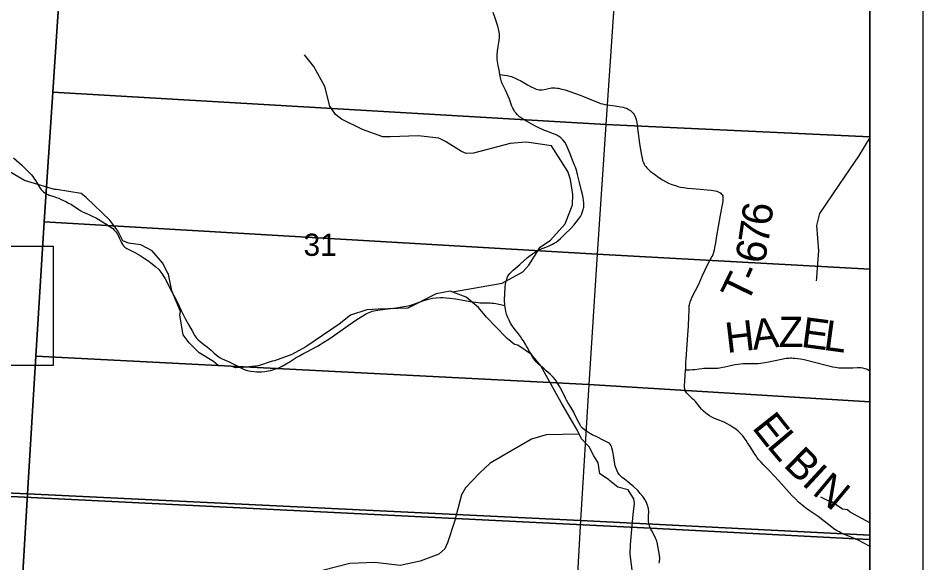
# Model space of a CAD drawing. Extents: x 0 to 34, y 0 to 22.
# Drawn here: x 7.297 to 9, y 19.136 to 20.161 of the extents above; entities that cross this region are included whole.
import ezdxf

# ---------------------------------------------------------------- set-up
doc = ezdxf.new("R2010")
doc.units = 0
for name, color, linetype in [('Default', 7, 'Continuous'), ('GM_X_County_Road', 7, 'Continuous'), ('GM_X_Minor_River', 7, 'Continuous'), ('GM_X_Section', 7, 'Continuous'), ('GM_X_Section_Text', 7, 'Continuous'), ('GM_X_Township_Road', 7, 'Continuous'), ('GM_X_Township_Road_Text', 7, 'Continuous'), ('SH_Cut_Line', 7, 'Continuous'), ('SH_Data', 7, 'Continuous'), ('TX_P_1', 7, 'Continuous')]:
    doc.layers.add(name, color=color, linetype=linetype)

msp = doc.modelspace()

# ---------------------------------------------------------------- linework, layer by layer
at = {"layer": 'Default'}
for points in [[(7.1944, 19.2649), (8.4872, 19.2008), (8.8731, 19.181), (8.9, 19.1797), (8.9, 20.9), (6.3694, 20.9)], [(8.9, 14.1), (8.9, 19.1797), (8.8731, 19.181), (8.4872, 19.2008), (7.1944, 19.2649), (6.2536, 19.3066), (6.2282, 18.9116), (6.1917, 18.3385), (6.1723, 18.0255), (6.1151, 17.0743), (6.0901, 16.6706), (6.0633, 16.2368)]]:
    msp.add_lwpolyline(points, dxfattribs=at)
for points in [[(8.9, 19.9376), (8.9, 20.1978), (8.4216, 20.2279), (8.4033, 19.9608)], [(8.9, 19.6886), (8.9, 19.9376), (8.4033, 19.9608), (8.3873, 19.7165)], [(8.9, 19.4386), (8.9, 19.6886), (8.3873, 19.7165), (8.3712, 19.4714)], [(8.9, 19.1878), (8.9, 19.4386), (8.3712, 19.4714), (8.3558, 19.2156)], [(8.9, 18.1799), (8.9, 19.1878), (8.3558, 19.2156), (8.299, 18.2095)]]:
    msp.add_lwpolyline(points, close=True, dxfattribs=at)
at = {"layer": 'GM_X_County_Road'}
for points in [[(8.2041, 20.0548), (8.2025, 20.0637), (8.2006, 20.0718), (8.1993, 20.0795), (8.1988, 20.0832), (8.1987, 20.0869), (8.1988, 20.091), (8.1996, 20.0992), (8.2009, 20.1078), (8.2021, 20.1151), (8.2027, 20.1197), (8.2029, 20.1237), (8.203, 20.1276), (8.2029, 20.1311), (8.2026, 20.1345), (8.2021, 20.1375), (8.2015, 20.1409), (8.2002, 20.1456), (8.1948, 20.1609), (8.1913, 20.1715)], [(8.2771, 19.5092), (8.2745, 19.5116), (8.2723, 19.5138), (8.2702, 19.5164), (8.2675, 19.52), (8.2645, 19.5249), (8.2616, 19.5302), (8.2598, 19.5335), (8.256, 19.5405), (8.2541, 19.5436), (8.2525, 19.5461), (8.2481, 19.5535), (8.2453, 19.5576), (8.2425, 19.5617), (8.2387, 19.5666), (8.2308, 19.5767), (8.2263, 19.583), (8.224, 19.5867), (8.2211, 19.5922), (8.2189, 19.5974), (8.2166, 19.6039), (8.2153, 19.6088), (8.2142, 19.6136), (8.2136, 19.617), (8.2132, 19.6201), (8.213, 19.6231), (8.2127, 19.6267), (8.2127, 19.6309), (8.2132, 19.6425), (8.2139, 19.6544), (8.2147, 19.6606), (8.2157, 19.666), (8.2167, 19.6693), (8.2177, 19.6722), (8.2191, 19.675), (8.2208, 19.6778), (8.2227, 19.6803), (8.225, 19.683), (8.2287, 19.6864), (8.2413, 19.6975), (8.2561, 19.7105), (8.261, 19.7144), (8.265, 19.7173), (8.2689, 19.7197), (8.273, 19.7221), (8.2773, 19.7243), (8.2838, 19.7272), (8.292, 19.7304), (8.2989, 19.7334), (8.3029, 19.7353), (8.3063, 19.7372), (8.3097, 19.7396), (8.3132, 19.7421), (8.3183, 19.7465), (8.3268, 19.7547), (8.3365, 19.7643), (8.3428, 19.7711), (8.3476, 19.7768), (8.352, 19.7827), (8.3554, 19.7879), (8.3579, 19.7928), (8.3596, 19.7968), (8.3609, 19.8008), (8.3614, 19.803), (8.3617, 19.805), (8.3621, 19.8092), (8.362, 19.8135), (8.3614, 19.8183), (8.3608, 19.8224), (8.3599, 19.8266), (8.3576, 19.8361), (8.3538, 19.8519), (8.3503, 19.8667), (8.3487, 19.872), (8.3473, 19.8766), (8.346, 19.8802), (8.3444, 19.8841), (8.3406, 19.8935), (8.3359, 19.9053), (8.3305, 19.9188), (8.3284, 19.9232), (8.326, 19.9275), (8.3226, 19.9318), (8.3208, 19.9337), (8.3188, 19.9355), (8.3157, 19.9379), (8.3131, 19.9395), (8.3111, 19.9407), (8.3088, 19.9417), (8.3059, 19.9428), (8.2952, 19.9467), (8.2916, 19.9481), (8.2879, 19.9496), (8.2841, 19.9513), (8.28, 19.9533), (8.2712, 19.9579), (8.2631, 19.9622), (8.2497, 19.9694), (8.2444, 19.9726), (8.2409, 19.9753), (8.2372, 19.9787), (8.2343, 19.9819), (8.2317, 19.9855), (8.2301, 19.9881), (8.2285, 19.9912), (8.2266, 19.9954), (8.2245, 20.0009), (8.2218, 20.0082), (8.2195, 20.0138), (8.217, 20.0198), (8.2144, 20.0252), (8.2117, 20.0304), (8.2093, 20.0354), (8.2076, 20.0389), (8.2068, 20.041), (8.2062, 20.0434), (8.2056, 20.0459), (8.2041, 20.0548)], [(8.4879, 19.1994), (8.4874, 19.2003), (8.4869, 19.2014), (8.4854, 19.2055), (8.4846, 19.2079), (8.4841, 19.2104), (8.4837, 19.2128), (8.4835, 19.2154), (8.4835, 19.2182), (8.4836, 19.2216), (8.4839, 19.226), (8.4841, 19.2303), (8.4841, 19.2339), (8.4839, 19.236), (8.4836, 19.238), (8.4831, 19.2402), (8.4825, 19.2422), (8.4812, 19.2457), (8.4796, 19.2493), (8.4766, 19.2552), (8.4729, 19.2609), (8.4682, 19.2665), (8.4633, 19.2719), (8.4552, 19.2797), (8.4499, 19.2841), (8.4447, 19.2882), (8.4383, 19.2931), (8.4339, 19.2967), (8.4303, 19.3002), (8.4286, 19.3021), (8.4271, 19.304), (8.4259, 19.3055), (8.425, 19.3072), (8.4237, 19.3099), (8.4225, 19.3133), (8.4211, 19.3186), (8.4197, 19.3253), (8.4176, 19.3382), (8.4169, 19.3425), (8.4158, 19.3479), (8.4147, 19.3521), (8.4137, 19.3549), (8.4127, 19.357), (8.4114, 19.3589), (8.41, 19.3605), (8.4082, 19.3619), (8.4061, 19.3632), (8.3998, 19.3663), (8.3849, 19.3733), (8.3777, 19.377), (8.3695, 19.3816), (8.3659, 19.384), (8.3629, 19.3863), (8.3591, 19.3895), (8.3571, 19.3917), (8.3555, 19.394), (8.3524, 19.3996), (8.3477, 19.4096), (8.3446, 19.4163), (8.343, 19.4195), (8.3414, 19.4224), (8.3376, 19.4289), (8.3317, 19.4376), (8.3293, 19.4417), (8.3273, 19.4458), (8.3204, 19.4604), (8.3157, 19.4692), (8.3119, 19.4755), (8.3083, 19.4805), (8.3044, 19.4852), (8.2987, 19.4908), (8.2913, 19.4974), (8.2874, 19.5006), (8.2833, 19.5041), (8.2777, 19.5086), (8.2771, 19.5092)], [(8.5037, 19.135), (8.5042, 19.1376), (8.5046, 19.14), (8.5048, 19.1418), (8.5048, 19.1435), (8.5047, 19.1458), (8.5046, 19.1477), (8.5042, 19.1501), (8.502, 19.1638), (8.5006, 19.1711), (8.4998, 19.174), (8.499, 19.1768), (8.498, 19.1796), (8.4968, 19.1821), (8.494, 19.1876), (8.4896, 19.1958), (8.4879, 19.1994)]]:
    msp.add_lwpolyline(points, dxfattribs=at)
at = {"layer": 'GM_X_Minor_River'}
for points in [[(7.4941, 19.7418), (7.4849, 19.7604), (7.4702, 19.7805), (7.4255, 19.8234), (7.4161, 19.8306), (7.3696, 19.8385), (7.3658, 19.8384), (7.3091, 19.8554), (7.2807, 19.8721), (7.2588, 19.8914), (7.2319, 19.9355), (7.2156, 19.9552), (7.2156, 19.9594), (7.1845, 20.011), (7.1739, 20.0315), (7.1743, 20.071), (7.1776, 20.1018), (7.1738, 20.1208), (7.1703, 20.1424)], [(8.1147, 19.6461), (8.208, 19.6622), (8.2472, 19.6833), (8.2585, 19.6959), (8.2799, 19.7298), (8.2989, 19.7428), (8.3266, 19.7735), (8.3406, 19.8095), (8.3411, 19.8292), (8.3367, 19.8575), (8.3315, 19.8721), (8.3008, 19.9209), (8.2583, 19.9268), (8.2526, 19.9274), (8.2235, 19.9249), (8.1545, 19.9069), (8.1405, 19.9063), (8.1319, 19.9099), (8.1015, 19.9288), (8.0892, 19.9349), (8.0504, 19.9395), (7.9978, 19.9378), (7.9835, 19.9378), (7.9453, 19.9516), (7.9058, 19.9707), (7.8944, 19.9794), (7.8839, 19.9953), (7.8744, 20.0321), (7.854, 20.0696), (7.8362, 20.0918)], [(8.9, 19.9363), (8.879, 19.9009), (8.853, 19.8638), (8.8052, 19.793), (8.7998, 19.7706), (8.8034, 19.7227), (8.8005, 19.682), (8.7997, 19.6714), (8.7989, 19.6664)], [(7.58, 19.679), (7.5788, 19.6808), (7.5693, 19.7002), (7.5493, 19.7229), (7.5281, 19.7343), (7.505, 19.7373), (7.4941, 19.7418)], [(8.2942, 19.4829), (8.2809, 19.5068), (8.2635, 19.5281), (8.2374, 19.5455), (8.2314, 19.5466), (8.2174, 19.558), (8.2151, 19.5603), (8.1788, 19.5982), (8.1636, 19.6164), (8.1402, 19.6361), (8.1103, 19.6471), (8.0839, 19.6421), (8.0306, 19.6153), (7.9746, 19.6129), (7.9538, 19.6121), (7.9225, 19.6022), (7.9017, 19.585), (7.839, 19.5423), (7.8122, 19.5278), (7.7797, 19.5159), (7.7751, 19.5152), (7.7494, 19.5067), (7.72, 19.5036), (7.7064, 19.5025), (7.6992, 19.5055), (7.6738, 19.5073), (7.6648, 19.5145), (7.6379, 19.5312), (7.619, 19.5498), (7.6076, 19.5649), (7.6019, 19.6022), (7.6027, 19.609), (7.5864, 19.6474), (7.58, 19.679)], [(8.4526, 19.1226), (8.4488, 19.1522), (8.4499, 19.1705), (8.4547, 19.2267), (8.4574, 19.2476), (8.4562, 19.2564), (8.4505, 19.2651), (8.4452, 19.2731), (8.4259, 19.2784), (8.4104, 19.2905), (8.4085, 19.2928), (8.3923, 19.303), (8.3889, 19.3239), (8.3805, 19.3372), (8.3722, 19.3542), (8.3574, 19.3694), (8.3499, 19.3846), (8.3192, 19.4374), (8.2942, 19.4829)], [(8.3531, 19.3781), (8.2909, 19.3769), (8.2632, 19.3688), (8.1857, 19.3236), (8.1655, 19.3044), (8.1395, 19.2768), (8.1319, 19.2639), (8.1187, 19.2138), (8.1056, 19.1732), (8.1003, 19.1622), (8.0888, 19.1521), (8.0539, 19.139), (8.0163, 19.1309), (7.9686, 19.1365), (7.9216, 19.1345), (7.8457, 19.1152), (7.8248, 19.1135), (7.8142, 19.1143), (7.8051, 19.117)], [(8.9, 19.2109), (8.8634, 19.2311), (8.8584, 19.2353), (8.849, 19.2368), (8.8248, 19.2534), (8.8218, 19.2527), (8.8078, 19.2591)]]:
    msp.add_lwpolyline(points, dxfattribs=at)
at = {"layer": 'GM_X_Section'}
for points in [[(6.3282, 20.3221), (7.3795, 20.2788), (7.3627, 20.0215), (7.3466, 19.7773), (7.3307, 19.5247), (7.3152, 19.2658), (6.2595, 19.3129)], [(8.4216, 20.2279), (8.4033, 19.9608), (7.3627, 20.0215), (7.3795, 20.2788)], [(7.3627, 20.0215), (8.4033, 19.9608), (8.3873, 19.7165), (7.3466, 19.7773)], [(8.3873, 19.7165), (8.3712, 19.4714), (7.3307, 19.5247), (7.3466, 19.7773)], [(7.3307, 19.5247), (8.3712, 19.4714), (8.3558, 19.2156), (7.3152, 19.2658)], [(6.2595, 19.3129), (7.3152, 19.2658), (7.2546, 18.2574), (6.1942, 18.2962)], [(8.3558, 19.2156), (8.299, 18.2095), (7.2546, 18.2574), (7.3152, 19.2658)]]:
    msp.add_lwpolyline(points, close=True, dxfattribs=at)
at = {"layer": 'GM_X_Township_Road'}
for points in [[(8.2041, 20.0548), (8.2125, 20.0536), (8.2177, 20.0527), (8.2228, 20.0517), (8.2255, 20.0509), (8.2283, 20.05), (8.2315, 20.0487), (8.2379, 20.0456), (8.2431, 20.0429), (8.2557, 20.0355), (8.263, 20.0316), (8.2685, 20.029), (8.2724, 20.0275), (8.2751, 20.0267), (8.2776, 20.0263), (8.2806, 20.0259), (8.2834, 20.026), (8.2872, 20.0265), (8.2927, 20.0278), (8.2985, 20.0291), (8.3012, 20.0295), (8.3043, 20.0296), (8.3076, 20.0296), (8.3109, 20.0294), (8.3139, 20.029), (8.3207, 20.0275), (8.3268, 20.0258), (8.3358, 20.0226), (8.3547, 20.0157), (8.3614, 20.0132)], [(8.3614, 20.0132), (8.372, 20.0092), (8.3825, 20.0049), (8.3898, 20.0019), (8.3934, 20.0005), (8.3972, 19.9994), (8.4015, 19.9984), (8.4107, 19.9969), (8.4206, 19.9956), (8.431, 19.994), (8.436, 19.9931), (8.4388, 19.9923), (8.4413, 19.9916), (8.4433, 19.9907), (8.4454, 19.9897), (8.4474, 19.9885), (8.4497, 19.9868), (8.452, 19.9848), (8.4547, 19.9822), (8.4565, 19.9797), (8.458, 19.9771), (8.4593, 19.9741), (8.4606, 19.97), (8.4617, 19.9645), (8.4625, 19.9593), (8.4631, 19.9536), (8.4642, 19.9444), (8.4655, 19.9345), (8.4666, 19.9253), (8.468, 19.9168), (8.4703, 19.9032), (8.4715, 19.8975), (8.4726, 19.8933), (8.4741, 19.8891), (8.4753, 19.8862), (8.4761, 19.8847), (8.4769, 19.8833), (8.4783, 19.8816), (8.4805, 19.8791), (8.4832, 19.8764), (8.4874, 19.8726), (8.4946, 19.867), (8.5031, 19.8611), (8.5098, 19.8568), (8.5158, 19.8532), (8.5214, 19.8506), (8.5277, 19.8479), (8.5341, 19.8457), (8.539, 19.8442), (8.5437, 19.843), (8.55, 19.8419), (8.5566, 19.8412), (8.5657, 19.8405), (8.581, 19.8392), (8.594, 19.8379), (8.6016, 19.837), (8.6056, 19.8365), (8.609, 19.8359), (8.6119, 19.8353), (8.6149, 19.8342), (8.6177, 19.8328), (8.6197, 19.8314), (8.6212, 19.8299), (8.6224, 19.8282), (8.6232, 19.8265), (8.6236, 19.8247), (8.6238, 19.822), (8.6236, 19.8191), (8.6232, 19.8156), (8.6216, 19.8062), (8.6187, 19.7903), (8.6147, 19.7686), (8.6117, 19.7513), (8.6095, 19.7382), (8.608, 19.7294), (8.6071, 19.7241), (8.6058, 19.7196), (8.6045, 19.7157), (8.6028, 19.7121), (8.5984, 19.7039), (8.5943, 19.6961), (8.5896, 19.6864), (8.5841, 19.6745), (8.5776, 19.6598), (8.5716, 19.6475), (8.5654, 19.636), (8.563, 19.6309), (8.5614, 19.6263), (8.5607, 19.624), (8.5602, 19.6215), (8.5598, 19.6192), (8.5596, 19.6167), (8.5592, 19.6109), (8.5589, 19.5991), (8.5582, 19.5814), (8.5573, 19.5651), (8.5565, 19.5552), (8.555, 19.5387), (8.5542, 19.527), (8.5537, 19.5201), (8.5535, 19.5129), (8.5531, 19.4993), (8.5615, 19.4992), (8.5661, 19.4994), (8.5706, 19.4997), (8.5791, 19.5007), (8.5846, 19.5016), (8.5879, 19.5019), (8.5911, 19.5022), (8.5956, 19.5022), (8.6052, 19.5021), (8.6104, 19.5022), (8.614, 19.5024), (8.6171, 19.5027), (8.6206, 19.5033), (8.627, 19.5046), (8.6378, 19.5071), (8.647, 19.5089), (8.6522, 19.5097), (8.657, 19.5104), (8.6615, 19.5108), (8.6657, 19.511), (8.6734, 19.511), (8.6817, 19.5108), (8.686, 19.5108), (8.6901, 19.511), (8.6943, 19.5113), (8.6981, 19.5119), (8.7026, 19.5126), (8.7096, 19.514), (8.722, 19.5168), (8.7337, 19.5192), (8.7428, 19.5207), (8.7474, 19.5212), (8.7502, 19.5214), (8.753, 19.5214), (8.7559, 19.5213), (8.7592, 19.5211), (8.7643, 19.5205), (8.7699, 19.5196), (8.7765, 19.5182), (8.7985, 19.5129), (8.8179, 19.5078), (8.8256, 19.5058), (8.83, 19.5048), (8.8355, 19.5038), (8.8417, 19.5031), (8.8491, 19.5026), (8.8534, 19.5025), (8.8578, 19.5026), (8.8684, 19.5031), (8.8771, 19.5034), (8.8833, 19.5032), (8.8864, 19.5028), (8.8906, 19.5018), (8.8931, 19.5009), (8.8952, 19.5), (8.8985, 19.4982), (8.9, 19.4972)], [(7.2884, 19.8983), (7.3044, 19.8842), (7.3102, 19.8786), (7.3146, 19.8744), (7.3188, 19.8698), (7.3224, 19.866), (7.3248, 19.863), (7.3269, 19.86), (7.3299, 19.8556), (7.3339, 19.8491), (7.3377, 19.8427), (7.34, 19.8392), (7.3425, 19.8364), (7.3452, 19.8338), (7.3478, 19.8319), (7.3495, 19.8308), (7.3513, 19.8299), (7.3537, 19.8289), (7.3559, 19.828), (7.3629, 19.8256), (7.3697, 19.8233), (7.3738, 19.8218), (7.3783, 19.8199), (7.3869, 19.8158), (7.3924, 19.8129), (7.3975, 19.81), (7.4118, 19.8006), (7.4155, 19.7983), (7.4199, 19.796), (7.4245, 19.7938), (7.4289, 19.7918), (7.4339, 19.7895), (7.4445, 19.7844), (7.4564, 19.7777), (7.4656, 19.7721), (7.4706, 19.7684), (7.4753, 19.7648), (7.4783, 19.7621), (7.4812, 19.7588), (7.4838, 19.7553), (7.4855, 19.7521), (7.4877, 19.7472), (7.4903, 19.7414), (7.4918, 19.7378), (7.4937, 19.7346), (7.4957, 19.7321), (7.4982, 19.7297), (7.5016, 19.7274), (7.5055, 19.7253), (7.517, 19.7197), (7.527, 19.7143), (7.5347, 19.7095), (7.5417, 19.7048), (7.5494, 19.6988), (7.5565, 19.6928), (7.5618, 19.6876), (7.5659, 19.683), (7.5678, 19.6804), (7.5699, 19.6774), (7.5733, 19.6715), (7.577, 19.6646), (7.583, 19.6526), (7.5903, 19.6392), (7.5935, 19.6334), (7.5968, 19.6267), (7.6043, 19.6105), (7.6121, 19.5945), (7.6177, 19.5841), (7.6246, 19.5723), (7.63, 19.5633), (7.6319, 19.5603), (7.6338, 19.5579), (7.6359, 19.5556), (7.6393, 19.5527), (7.6465, 19.5469), (7.6534, 19.5415), (7.6567, 19.5389), (7.661, 19.5354), (7.6659, 19.531), (7.6706, 19.5269), (7.6747, 19.5238), (7.6777, 19.5219), (7.6813, 19.5199), (7.6957, 19.5133), (7.7093, 19.5065), (7.7178, 19.5022), (7.7229, 19.4999), (7.7281, 19.498), (7.7312, 19.4972), (7.7348, 19.4965), (7.7412, 19.4956), (7.7463, 19.4952), (7.7508, 19.4952), (7.7553, 19.4954), (7.7618, 19.4961), (7.7681, 19.497), (7.7722, 19.4979), (7.7765, 19.4989), (7.7816, 19.5006), (7.788, 19.5031), (7.7939, 19.5059), (7.8092, 19.5149), (7.8207, 19.5221), (7.8266, 19.5254), (7.8329, 19.529), (7.8406, 19.5329), (7.8604, 19.5436), (7.8658, 19.5469), (7.8716, 19.5504), (7.8818, 19.5569), (7.899, 19.5687), (7.9182, 19.5825), (7.935, 19.5938), (7.9463, 19.6009), (7.9512, 19.6039), (7.9549, 19.6057), (7.9578, 19.607), (7.9608, 19.6082), (7.9637, 19.6092), (7.967, 19.61), (7.97, 19.6107), (7.9741, 19.6115), (7.9786, 19.6122), (7.9871, 19.6133), (8.0093, 19.616), (8.0197, 19.6175), (8.0276, 19.6187), (8.0314, 19.6194), (8.0347, 19.6202), (8.0384, 19.6212), (8.042, 19.6224), (8.0472, 19.6242), (8.0611, 19.6298), (8.067, 19.6317), (8.0719, 19.6329), (8.0774, 19.6339), (8.0843, 19.6345), (8.0924, 19.6349), (8.0967, 19.6349), (8.1029, 19.6346), (8.1098, 19.634), (8.1202, 19.6325), (8.135, 19.6299), (8.1509, 19.6272), (8.1582, 19.6262), (8.1631, 19.6257), (8.1668, 19.6253), (8.1724, 19.6251), (8.1774, 19.625), (8.1854, 19.6249), (8.189, 19.6247), (8.1924, 19.6244), (8.1966, 19.6237), (8.2051, 19.6219), (8.2132, 19.6201)], [(8.8741, 19.1801), (8.8733, 19.1805), (8.8691, 19.1824), (8.8575, 19.1871), (8.8477, 19.1913), (8.8422, 19.194), (8.8373, 19.1968), (8.8326, 19.1998), (8.8252, 19.2055), (8.8149, 19.2135), (8.8026, 19.2229), (8.786, 19.2344), (8.7792, 19.2392), (8.7758, 19.2418), (8.7723, 19.2448), (8.7661, 19.2502), (8.76, 19.2561), (8.7541, 19.2621), (8.7484, 19.2683), (8.7288, 19.29), (8.7194, 19.3004), (8.7114, 19.3088), (8.7049, 19.3154), (8.6991, 19.3209), (8.6954, 19.325), (8.6915, 19.3296), (8.6883, 19.3337), (8.6853, 19.3378), (8.6825, 19.3424), (8.6787, 19.3482), (8.6744, 19.3553), (8.6702, 19.3618), (8.6673, 19.3662), (8.6643, 19.3705), (8.6609, 19.3747), (8.6568, 19.3793), (8.6522, 19.3836), (8.6478, 19.3873), (8.6427, 19.3908), (8.6373, 19.3942), (8.6319, 19.3974), (8.6257, 19.4003), (8.6127, 19.4057), (8.6076, 19.4076), (8.6025, 19.41), (8.5981, 19.4126), (8.5941, 19.4154), (8.5906, 19.418), (8.5871, 19.4212), (8.5835, 19.4251), (8.5788, 19.4307), (8.5718, 19.4392), (8.5693, 19.4419), (8.5667, 19.4446), (8.5598, 19.4511), (8.5569, 19.4541), (8.5552, 19.456), (8.554, 19.4578), (8.5529, 19.4597), (8.5522, 19.4614), (8.5517, 19.4633), (8.5514, 19.4661), (8.5514, 19.4692), (8.5526, 19.4879), (8.5531, 19.4993)], [(8.9, 19.1665), (8.898, 19.1676), (8.8862, 19.1743), (8.8792, 19.1778), (8.8741, 19.1801)]]:
    msp.add_lwpolyline(points, dxfattribs=at)
at = {"layer": 'SH_Cut_Line'}
msp.add_lwpolyline([(8.9, 14.1), (8.9, 20.9), (2.1, 20.9), (2.1, 14.1)], dxfattribs=at)
at = {"layer": 'SH_Data'}
for p, q in [((9, 21), (9, 14)), ((8.9, 20.9), (8.9, 14.1))]:
    msp.add_line(p, q, dxfattribs=at)
at = {"layer": 'TX_P_1'}
msp.add_lwpolyline([(6.0281, 19.7319), (7.3634, 19.7319), (7.3634, 19.5074), (6.0281, 19.5074)], close=True, dxfattribs=at)

# ---------------------------------------------------------------- texts
at = {"layer": 'GM_X_Section_Text'}
msp.add_text('31', height=0.04186, rotation=0, dxfattribs=at).set_placement((7.8345, 19.7135))
at = {"layer": 'GM_X_Township_Road_Text'}
for s, rotation, p in [('6', 82.0801, (8.7137, 19.7684)), ('7', 81.6652, (8.7086, 19.7333)), ('6', 79.5431, (8.7018, 19.6967)), ('T', 63.9936, (8.6686, 19.6212)), ('-', 66.381, (8.6883, 19.6617)), ('Z', 0.3086, (8.7288, 19.542)), ('H', 6.6614, (8.6311, 19.5307)), ('A', 6.4943, (8.6807, 19.5365)), ('E', 352.4981, (8.7692, 19.5424)), ('L', 352.2796, (8.8113, 19.5368)), ('E', 308.4584, (8.677, 19.3898)), ('L', 310.3001, (8.7047, 19.355)), ('B', 315.1923, (8.7357, 19.3188)), ('I', 317.2544, (8.7704, 19.2844)), ('N', 320.1229, (8.7898, 19.2666))]:
    msp.add_text(s, height=0.0568, rotation=rotation, dxfattribs=at).set_placement(p)

doc.saveas('drawing.dxf')
